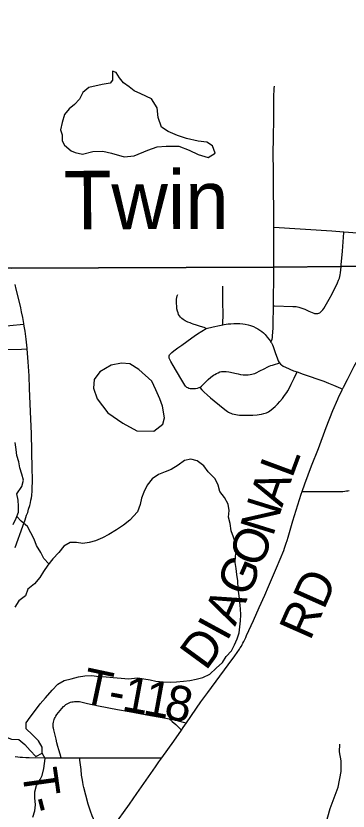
# Model space of a CAD drawing. Extents: x 0 to 34, y 0 to 22.
# Drawn here: x 3.067 to 3.606, y 16.327 to 17.616 of the extents above; entities that cross this region are included whole.
import ezdxf

# ---------------------------------------------------------------- set-up
doc = ezdxf.new("R2010")
doc.units = 0
for name, color, linetype in [('GM_X_City_Street', 7, 'Continuous'), ('GM_X_Corporation', 7, 'Continuous'), ('GM_X_County_Road', 7, 'Continuous'), ('GM_X_County_Road_Text', 7, 'Continuous'), ('GM_X_Minor_Lake', 7, 'Continuous'), ('GM_X_Minor_Lake_Text', 7, 'Continuous'), ('GM_X_Minor_River', 7, 'Continuous'), ('GM_X_State_Route', 7, 'Continuous'), ('GM_X_Township_Road', 7, 'Continuous'), ('GM_X_Township_Road_Text', 7, 'Continuous')]:
    doc.layers.add(name, color=color, linetype=linetype)

msp = doc.modelspace()

# ---------------------------------------------------------------- linework, layer by layer
at = {"layer": 'GM_X_City_Street'}
for points in [[(3.4853, 17.2733), (3.4851, 17.2894), (3.4851, 17.3055), (3.4849, 17.329), (3.4845, 17.3675), (3.4843, 17.3896), (3.4847, 17.4212), (3.4853, 17.446), (3.4852, 17.4846), (3.4854, 17.4884), (3.4856, 17.4937), (3.4859, 17.4978), (3.4864, 17.5016)], [(3.4853, 17.2733), (3.5792, 17.2674), (3.5989, 17.2659), (3.6499, 17.2621), (3.7323, 17.2558), (3.7541, 17.2539)]]:
    msp.add_lwpolyline(points, dxfattribs=at)
at = {"layer": 'GM_X_Corporation'}
for points in [[(2.114, 20.6173), (2.114, 17.2048), (2.159, 17.2055), (2.5952, 17.2097), (2.6493, 17.2102), (3.0597, 17.2067), (3.4848, 17.2088), (3.5941, 17.2097), (3.7259, 17.2107), (4.732, 17.2135)], [(4.732, 17.2135), (3.7259, 17.2107), (3.5941, 17.2097), (3.4848, 17.2088), (3.0597, 17.2067), (2.6493, 17.2102), (2.5952, 17.2097), (2.159, 17.2055), (2.114, 17.2048), (2.114, 13.8173), (5.0539, 13.8173)], [(3.0597, 17.2067), (3.4848, 17.2088), (3.5941, 17.2097), (3.7259, 17.2107)]]:
    msp.add_lwpolyline(points, dxfattribs=at)
at = {"layer": 'GM_X_County_Road'}
msp.add_line((3.1406, 16.4137), (3.1707, 16.4138), dxfattribs=at)
for points in [[(3.5966, 17.011), (3.5982, 17.0143), (3.6001, 17.018), (3.602, 17.0219), (3.6044, 17.0265), (3.6156, 17.048), (3.6233, 17.0622), (3.6301, 17.0748), (3.6469, 17.106), (3.6546, 17.1209), (3.6566, 17.1246), (3.6588, 17.1286), (3.6606, 17.1315), (3.6625, 17.1344), (3.6655, 17.1385), (3.6691, 17.1434), (3.6717, 17.1467), (3.6751, 17.151), (3.6786, 17.1555), (3.6985, 17.1774), (3.7116, 17.1921), (3.7144, 17.1954)], [(3.5313, 16.8452), (3.5357, 16.8574), (3.5465, 16.8865), (3.5574, 16.9149), (3.57, 16.9487), (3.5811, 16.9764), (3.5888, 16.9947), (3.5908, 16.9991), (3.5932, 17.0041), (3.5959, 17.0096), (3.5966, 17.011)], [(3.344, 16.4703), (3.3672, 16.5042), (3.3783, 16.5192), (3.4115, 16.5643), (3.4221, 16.5788), (3.4294, 16.5895), (3.4309, 16.592), (3.4326, 16.5947), (3.434, 16.5974), (3.4352, 16.5995), (3.4364, 16.602), (3.4381, 16.6053), (3.4397, 16.6086), (3.4412, 16.6118), (3.4523, 16.636), (3.4614, 16.6571), (3.4704, 16.677), (3.4764, 16.6911), (3.4894, 16.7212), (3.5012, 16.7495), (3.5025, 16.7532), (3.5038, 16.7567), (3.5055, 16.7614), (3.5069, 16.7659), (3.5084, 16.7709), (3.5158, 16.7978), (3.5298, 16.841), (3.5313, 16.8452)], [(3.3357, 16.4583), (3.3386, 16.4625), (3.344, 16.4703)], [(3.3036, 16.4133), (3.3234, 16.4406), (3.3357, 16.4583)], [(3.0662, 16.4159), (3.0706, 16.4152), (3.0744, 16.4149), (3.0781, 16.4145), (3.0835, 16.4143), (3.0887, 16.4141), (3.1148, 16.4136), (3.1406, 16.4137)], [(3.1707, 16.4138), (3.178, 16.4138), (3.2004, 16.4137), (3.2646, 16.4137), (3.3036, 16.4133)], [(3.2132, 16.2844), (3.2251, 16.3015), (3.2512, 16.3386), (3.2632, 16.3557), (3.282, 16.3827), (3.2934, 16.3989), (3.2991, 16.407), (3.3036, 16.4133)]]:
    msp.add_lwpolyline(points, dxfattribs=at)
at = {"layer": 'GM_X_Minor_Lake'}
for p, q in [((3.1423, 17.423), (3.142, 17.4131)), ((3.2877, 17.024), (3.2663, 17.0428))]:
    msp.add_line(p, q, dxfattribs=at)
for points in [[(3.142, 17.4131), (3.1458, 17.4063), (3.1568, 17.3973), (3.1633, 17.3943), (3.1754, 17.3918), (3.1917, 17.3957), (3.2083, 17.3966), (3.222, 17.3933), (3.2425, 17.3874), (3.2587, 17.389), (3.2813, 17.3983), (3.2964, 17.4033), (3.3108, 17.4046), (3.3313, 17.4044), (3.3483, 17.398), (3.3624, 17.3913), (3.3787, 17.3865), (3.39, 17.3931), (3.3861, 17.4052), (3.3766, 17.4112), (3.3626, 17.4126), (3.344, 17.417), (3.3289, 17.4218), (3.314, 17.4285), (3.303, 17.4356), (3.298, 17.4508), (3.296, 17.4667), (3.2871, 17.4814), (3.27, 17.4896), (3.259, 17.4941), (3.2507, 17.5008), (3.2419, 17.5072), (3.235, 17.5155), (3.2297, 17.5238), (3.2236, 17.526), (3.2237, 17.5116), (3.2203, 17.5067), (3.2071, 17.5043), (3.1856, 17.4996), (3.1758, 17.4915), (3.1706, 17.4809), (3.1623, 17.4721), (3.1537, 17.4652), (3.1462, 17.456), (3.1421, 17.4431), (3.1395, 17.4313), (3.1423, 17.423)], [(3.2663, 17.0428), (3.2519, 17.0518), (3.2386, 17.0529), (3.2216, 17.0497), (3.2035, 17.0389), (3.1942, 17.0263), (3.1928, 17.0123), (3.1989, 16.9953), (3.2165, 16.9727), (3.2405, 16.9558), (3.2633, 16.9435), (3.2909, 16.9429), (3.3056, 16.9544), (3.3082, 16.9647), (3.305, 16.9832), (3.3004, 16.9953), (3.2942, 17.0097), (3.2877, 17.024)], [(3.0628, 16.7917), (3.0676, 16.802), (3.0717, 16.8115), (3.0716, 16.8214), (3.0712, 16.8309), (3.0688, 16.8415), (3.0767, 16.8533), (3.0796, 16.8632), (3.0769, 16.8734), (3.0734, 16.8832), (3.0718, 16.8931), (3.0687, 16.9033), (3.0675, 16.9131), (3.0659, 16.9245)], [(3.1096, 16.4209), (3.1099, 16.4311), (3.1037, 16.4413), (3.0934, 16.4511), (3.0839, 16.4605), (3.0838, 16.47), (3.0902, 16.4795), (3.0992, 16.4906), (3.1067, 16.5008), (3.1153, 16.5108), (3.1262, 16.523), (3.1352, 16.5329), (3.1454, 16.5391), (3.1567, 16.5414), (3.1688, 16.5449), (3.179, 16.5462), (3.19, 16.547), (3.2021, 16.5452), (3.2138, 16.5449), (3.2248, 16.5435), (3.2377, 16.5428), (3.2498, 16.5418), (3.2642, 16.543), (3.2748, 16.5416), (3.2846, 16.5398), (3.2941, 16.5379), (3.3059, 16.5369), (3.3176, 16.5362), (3.3274, 16.5367), (3.3388, 16.5379), (3.349, 16.5388), (3.3592, 16.5411), (3.3701, 16.5438), (3.3815, 16.5492), (3.3916, 16.5588), (3.4021, 16.568), (3.4081, 16.5775), (3.4164, 16.5871), (3.4216, 16.5966), (3.426, 16.6061), (3.429, 16.616), (3.4304, 16.6258), (3.4315, 16.6357), (3.4318, 16.6452), (3.4313, 16.6547), (3.4301, 16.6657), (3.4293, 16.6763), (3.4277, 16.6876), (3.4268, 16.7001), (3.4252, 16.7104), (3.424, 16.7202), (3.4224, 16.7301), (3.4231, 16.7403), (3.4245, 16.7502), (3.4229, 16.7608), (3.4198, 16.771), (3.4163, 16.7816), (3.4144, 16.7933), (3.4116, 16.8035), (3.4127, 16.8142), (3.4115, 16.8248), (3.4053, 16.8353), (3.3977, 16.8451), (3.395, 16.8554), (3.39, 16.8656), (3.3789, 16.8768), (3.3716, 16.8867), (3.361, 16.8945), (3.3507, 16.8975), (3.3405, 16.8951), (3.33, 16.8875), (3.3187, 16.8806), (3.3089, 16.8771), (3.2983, 16.8728), (3.2881, 16.8655), (3.2799, 16.8556), (3.2747, 16.8438), (3.271, 16.8343), (3.2688, 16.824), (3.2643, 16.8123), (3.252, 16.7989), (3.2414, 16.7908), (3.2301, 16.7832), (3.2181, 16.7755), (3.2075, 16.7701), (3.1962, 16.7651), (3.186, 16.7627), (3.1758, 16.7608), (3.1656, 16.7622), (3.1553, 16.7625), (3.1452, 16.7563), (3.1369, 16.7464), (3.1272, 16.7361), (3.1193, 16.7258), (3.1118, 16.7155), (3.1062, 16.7056), (3.0972, 16.6957), (3.0867, 16.6869), (3.0826, 16.6762), (3.0721, 16.6678), (3.0653, 16.6579)], [(3.0273, 16.5844), (3.0247, 16.5745), (3.0157, 16.5646), (3.0075, 16.5535), (3.003, 16.5429), (2.9993, 16.5307), (2.9975, 16.5212), (3.0003, 16.5099), (3.0075, 16.4993), (3.0156, 16.4888), (3.0213, 16.479), (3.0305, 16.468), (3.0393, 16.4582), (3.0503, 16.4477), (3.0602, 16.4436), (3.0723, 16.4433), (3.0818, 16.4354), (3.0902, 16.4256), (3.0998, 16.4159), (3.1096, 16.4209)]]:
    msp.add_lwpolyline(points, dxfattribs=at)
at = {"layer": 'GM_X_Minor_River'}
for points in [[(3.1208, 16.7278), (3.1128, 16.7364), (3.1078, 16.7462), (3.1005, 16.7575), (3.097, 16.7681), (3.0913, 16.7783), (3.0863, 16.7885), (3.076, 16.7971), (3.0686, 16.8044)], [(3.5519, 16.2487), (3.5573, 16.278), (3.5688, 16.3042), (3.5766, 16.3312), (3.5895, 16.3662), (3.5946, 16.3916), (3.5941, 16.4087), (3.5917, 16.4231), (3.592, 16.4356)], [(3.0949, 16.3176), (3.0978, 16.3275), (3.0993, 16.3374), (3.098, 16.3487), (3.098, 16.3586), (3.1005, 16.3688), (3.1067, 16.3782), (3.11, 16.3848), (3.1128, 16.3964), (3.1146, 16.4123), (3.1096, 16.4209)]]:
    msp.add_lwpolyline(points, dxfattribs=at)
at = {"layer": 'GM_X_State_Route'}
msp.add_lwpolyline([(3.0663, 16.7543), (3.0787, 16.7888), (3.0822, 16.7992), (3.0847, 16.8065), (3.0864, 16.8112), (3.0879, 16.8165), (3.0897, 16.8225), (3.0907, 16.8266), (3.0917, 16.831), (3.0924, 16.8348), (3.093, 16.8385), (3.0937, 16.846), (3.094, 16.8659), (3.0939, 16.8815), (3.0932, 16.9107), (3.0924, 16.9386), (3.0908, 16.9747), (3.0896, 17.0119), (3.0886, 17.0325), (3.0871, 17.0554), (3.0854, 17.076), (3.0853, 17.0771), (3.0839, 17.0917), (3.0822, 17.1049), (3.0811, 17.1104), (3.0803, 17.1162), (3.0802, 17.1172), (3.0784, 17.127), (3.0766, 17.1363), (3.0752, 17.1424), (3.074, 17.1477), (3.0677, 17.1731), (3.066, 17.1805)], dxfattribs=at)
at = {"layer": 'GM_X_Township_Road'}
for points in [[(3.485, 17.2082), (3.485, 17.2209), (3.4851, 17.2627), (3.4853, 17.2733)], [(3.5943, 17.2091), (3.5946, 17.2124), (3.5964, 17.2344), (3.5988, 17.2646), (3.5989, 17.2659)], [(3.4847, 17.1459), (3.4865, 17.1458), (3.5162, 17.145), (3.5188, 17.1449), (3.5212, 17.1446), (3.5259, 17.1437), (3.5291, 17.1429), (3.5321, 17.1418), (3.5356, 17.1403), (3.5417, 17.1375), (3.5499, 17.1341), (3.5512, 17.1337), (3.5529, 17.1334), (3.5546, 17.1334), (3.5564, 17.1336), (3.5584, 17.1341), (3.5598, 17.1347), (3.5611, 17.1357), (3.5622, 17.1367), (3.5631, 17.1377), (3.5647, 17.1395), (3.5662, 17.1416), (3.5748, 17.1568), (3.5796, 17.1655), (3.5884, 17.1832), (3.5902, 17.1874), (3.5915, 17.1908), (3.5923, 17.1935), (3.5928, 17.196), (3.5934, 17.1996), (3.5943, 17.2091)], [(3.4847, 17.1459), (3.4849, 17.1574), (3.4851, 17.191), (3.485, 17.2082)], [(3.4028, 17.1153), (3.4028, 17.1168), (3.4029, 17.1322), (3.4027, 17.1519), (3.4026, 17.1699), (3.4027, 17.1779)], [(3.3754, 17.109), (3.3722, 17.1106), (3.3662, 17.1126), (3.3601, 17.1146), (3.3546, 17.1164), (3.3519, 17.1173), (3.3495, 17.1181), (3.346, 17.1195), (3.3416, 17.1217), (3.3384, 17.1238), (3.336, 17.1254), (3.3338, 17.1276), (3.3324, 17.1295), (3.331, 17.132), (3.3302, 17.1344), (3.3292, 17.1375), (3.3283, 17.1409), (3.3278, 17.1453), (3.3275, 17.1495), (3.3277, 17.1569), (3.3279, 17.1595), (3.3286, 17.1621), (3.3296, 17.1644)], [(3.4806, 17.0873), (3.4817, 17.0893), (3.4825, 17.092), (3.4829, 17.0948), (3.4832, 17.0975), (3.4839, 17.1096), (3.4842, 17.1158), (3.4847, 17.1459)], [(3.0029, 17.1079), (3.0128, 17.109), (3.0302, 17.1108), (3.0368, 17.1116), (3.0468, 17.1128), (3.0626, 17.1144), (3.074, 17.1155), (3.0803, 17.1162)], [(3.3754, 17.109), (3.3871, 17.112), (3.3973, 17.1143), (3.4028, 17.1153)], [(3.4028, 17.1153), (3.4047, 17.1156), (3.411, 17.1165), (3.4158, 17.117), (3.4204, 17.1173), (3.4252, 17.1174), (3.4302, 17.1171), (3.435, 17.1167), (3.4389, 17.1162), (3.4438, 17.1151), (3.4475, 17.114), (3.4522, 17.1124), (3.456, 17.1105), (3.4592, 17.1089), (3.4628, 17.1067), (3.4659, 17.1045), (3.4687, 17.1022), (3.471, 17.0996), (3.4747, 17.0953), (3.4774, 17.0919), (3.48, 17.0884), (3.4806, 17.0873)], [(3.3162, 17.0664), (3.3172, 17.0678), (3.3181, 17.0688), (3.3197, 17.0702), (3.3234, 17.0731), (3.3298, 17.0778), (3.3363, 17.0824), (3.3441, 17.088), (3.3522, 17.0939), (3.3562, 17.0967), (3.3617, 17.1004), (3.3688, 17.1049), (3.3754, 17.109)], [(3.4806, 17.0873), (3.4814, 17.086), (3.4829, 17.0826), (3.4839, 17.0798), (3.4872, 17.0702), (3.491, 17.0601), (3.4923, 17.0569), (3.4937, 17.0541), (3.4942, 17.0534)], [(3.0406, 17.0738), (3.0416, 17.0743), (3.0424, 17.0746), (3.0432, 17.0748), (3.0444, 17.075), (3.0458, 17.0751), (3.0514, 17.0753), (3.0764, 17.0758), (3.0854, 17.076)], [(3.3656, 17.0136), (3.3635, 17.0128), (3.3611, 17.0121), (3.3582, 17.0115), (3.3548, 17.0112), (3.3517, 17.0112), (3.3495, 17.0116), (3.3477, 17.0121), (3.3459, 17.0128), (3.3445, 17.0136), (3.3434, 17.0147), (3.3422, 17.0159), (3.341, 17.0176), (3.3346, 17.028), (3.3221, 17.0494), (3.3185, 17.0559), (3.3158, 17.0613), (3.3155, 17.0626), (3.3154, 17.0639), (3.3157, 17.0651), (3.3162, 17.0664)], [(3.3656, 17.0136), (3.3679, 17.0158), (3.376, 17.024), (3.379, 17.0267), (3.3832, 17.0301), (3.3874, 17.0333), (3.3897, 17.0348), (3.3922, 17.0362), (3.3949, 17.0376), (3.3979, 17.0387), (3.4007, 17.0393), (3.4035, 17.0396), (3.4058, 17.0396), (3.408, 17.0394), (3.4123, 17.0389), (3.4245, 17.0363), (3.4273, 17.0356), (3.431, 17.0349), (3.4358, 17.0343), (3.4394, 17.034), (3.4417, 17.034), (3.4438, 17.0341), (3.4471, 17.0345), (3.4497, 17.035), (3.452, 17.0356), (3.4544, 17.0364), (3.4577, 17.0378), (3.4615, 17.0398), (3.4704, 17.0445), (3.4743, 17.0465), (3.4775, 17.048), (3.4802, 17.049), (3.4829, 17.0499), (3.4862, 17.051), (3.4935, 17.0532), (3.4942, 17.0534)], [(3.4942, 17.0534), (3.4958, 17.0515), (3.4976, 17.0501), (3.5006, 17.0483), (3.504, 17.0465), (3.5171, 17.0408), (3.523, 17.0387)], [(3.3656, 17.0136), (3.3685, 17.01), (3.3721, 17.0062), (3.3771, 17.0017), (3.3828, 16.9967), (3.3883, 16.9919), (3.3973, 16.9847), (3.403, 16.9802), (3.4082, 16.9763), (3.4101, 16.9748), (3.4119, 16.9736), (3.4137, 16.9726), (3.4157, 16.9718), (3.418, 16.971), (3.4209, 16.9702), (3.4236, 16.9696), (3.4266, 16.9693), (3.4297, 16.969), (3.4366, 16.9686), (3.4427, 16.9686), (3.4511, 16.969), (3.4581, 16.9694), (3.4616, 16.9698), (3.4655, 16.9704), (3.4691, 16.9712), (3.4733, 16.9726), (3.4764, 16.9743), (3.479, 16.9758), (3.481, 16.9774), (3.4841, 16.98), (3.4873, 16.9828), (3.491, 16.9864), (3.4952, 16.991), (3.4994, 16.9958), (3.5028, 17.0004), (3.5061, 17.0053), (3.5077, 17.0081), (3.51, 17.0119), (3.5136, 17.0189), (3.5184, 17.0288), (3.5226, 17.0377), (3.523, 17.0387)], [(3.523, 17.0387), (3.5329, 17.0351), (3.5664, 17.0236), (3.5739, 17.0208), (3.5819, 17.0176), (3.5935, 17.0124), (3.5966, 17.011)], [(3.5313, 16.8452), (3.5373, 16.8452), (3.56, 16.845), (3.578, 16.845), (3.5935, 16.8451), (3.597, 16.8453), (3.6002, 16.8455), (3.603, 16.8459), (3.605, 16.8462), (3.6075, 16.8466)], [(3.1406, 16.4137), (3.1389, 16.4196), (3.137, 16.4263), (3.1354, 16.4317), (3.1338, 16.4378), (3.1323, 16.4439), (3.1286, 16.4588), (3.1281, 16.4614), (3.1279, 16.4635), (3.1278, 16.465), (3.1278, 16.467), (3.1279, 16.4689), (3.1283, 16.4714), (3.1287, 16.4737), (3.1292, 16.4754), (3.1298, 16.4771), (3.1308, 16.4791), (3.1319, 16.4811), (3.1334, 16.4835), (3.1416, 16.4936), (3.1446, 16.4968), (3.1458, 16.498), (3.1469, 16.4989), (3.1482, 16.4998), (3.1494, 16.5006), (3.1516, 16.5018), (3.1537, 16.5027), (3.156, 16.5035), (3.1581, 16.5042), (3.1602, 16.5045), (3.1624, 16.5048), (3.1645, 16.505), (3.1663, 16.505), (3.1682, 16.5049), (3.1702, 16.5047), (3.1725, 16.5043), (3.1834, 16.5016), (3.2009, 16.498), (3.2319, 16.492), (3.251, 16.4886), (3.2853, 16.4822), (3.3104, 16.4777), (3.3159, 16.4765)], [(3.3159, 16.4765), (3.3262, 16.4744), (3.3383, 16.4716), (3.344, 16.4703)], [(3.3159, 16.4765), (3.3207, 16.4723), (3.3262, 16.4674), (3.3323, 16.4615), (3.3357, 16.4583)], [(3.2024, 16.287), (3.202, 16.2896), (3.2012, 16.2924), (3.2003, 16.2956), (3.1993, 16.2989), (3.198, 16.3029), (3.1965, 16.3068), (3.1946, 16.3111), (3.193, 16.3149), (3.191, 16.3198), (3.1881, 16.3273), (3.1845, 16.3385), (3.1804, 16.3529), (3.1772, 16.3655), (3.1763, 16.3698), (3.1755, 16.3741), (3.1746, 16.3798), (3.1737, 16.3857), (3.1728, 16.3947), (3.1711, 16.4099), (3.1707, 16.4138)]]:
    msp.add_lwpolyline(points, dxfattribs=at)

# ---------------------------------------------------------------- texts
at = {"layer": 'GM_X_County_Road_Text'}
for s, height, rotation, p in [('L', 0.0568, 69.6173, (3.5147, 16.8653)), ('A', 0.0568, 71.1095, (3.4986, 16.8182)), ('N', 0.0568, 72.72, (3.4838, 16.7707)), ('O', 0.0568, 68.3826, (3.4638, 16.7197)), ('G', 0.0568, 66.5423, (3.4431, 16.6718)), ('RD', 0.05682, 66.0867, (3.544, 16.6019)), ('A', 0.0568, 65.9618, (3.4224, 16.6255)), ('I', 0.0568, 61.4733, (3.4092, 16.6008)), ('D', 0.0568, 53.8519, (3.3752, 16.5533))]:
    msp.add_text(s, height=height, rotation=rotation, dxfattribs=at).set_placement(p)
at = {"layer": 'GM_X_Minor_Lake_Text'}
msp.add_text('Twin', height=0.09474, rotation=0.1732, dxfattribs=at).set_placement((3.1448, 17.2698))
at = {"layer": 'GM_X_Township_Road_Text'}
for s, rotation, p in [('T', 347.9984, (3.1714, 16.5045)), ('1', 349.5459, (3.2373, 16.4911)), ('1', 349.6089, (3.2715, 16.4848)), ('8', 347.8666, (3.3052, 16.4786)), ('-', 349.4107, (3.2144, 16.4953)), ('T', 277.9213, (3.0769, 16.3934)), ('-', 284.5684, (3.0842, 16.3443))]:
    msp.add_text(s, height=0.0568, rotation=rotation, dxfattribs=at).set_placement(p)

doc.saveas('drawing.dxf')
